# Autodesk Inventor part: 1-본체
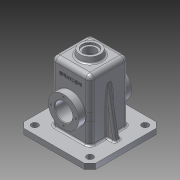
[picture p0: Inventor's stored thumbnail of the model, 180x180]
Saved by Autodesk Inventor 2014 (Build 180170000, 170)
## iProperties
Created: 2016-02
Part Number: 1-본체
Material: 알루미늄 6061
Document SubType Name: Modeling
Designer: 703-04
Density: 2.71 g/cm^3
Appearance: 알루미늄 - 평지
Mass: 932.849 g
Surface Area: 1043.49 cm^2
Volume: 344.225 cm^3
Author: 703-04
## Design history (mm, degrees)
sketch "스케치1"
  geometry: L1 (-65, 65)-(65, 65); L2 (65, 65)-(65, -65); L3 (65, -65)-(-65, -65); L4 (-65, -65)-(-65, 65); 1 further point
  constraints: 8 end point, 2 parallel, 1 horizontal, 1 perpendicular
  dimensions: "d0" = 130 distance of L2.end L3.end; "d1" = 65 distance from line of point (0, 0) L4; "d2" = 65 distance from line of point (0, 0) L1; "d3" = 130 distance between parallel lines of L3 L1
extrude "돌출1" new body sketch "스케치1" distance "d4" = 10; taper "d5" = 0 deg
chamfer "모따기1" distance "d6" = 10; stored, may be unused: second distance "d7" = 2, angle "d8" = 45 deg
sketch "스케치2"
  geometry: L1 (-35, 35)-(35, 35); L2 (35, 35)-(35, -35); L3 (35, -35)-(-35, -35); L4 (-35, -35)-(-35, 35); 1 further point
  constraints: 8 end point, 2 parallel, 1 horizontal, 1 perpendicular
  dimensions: "d9" = 35 distance from line of point (0, 0) L1; "d10" = 70 distance between parallel lines of L3 L1; "d11" = 35 distance from line of point (0, 0) L4; "d12" = 70 distance between parallel lines of L2 L4
extrude "돌출2" join sketch "스케치2" distance "d13" = 110; taper "d14" = 0 deg
node "작업 평면1"
sketch "스케치4"
  geometry: L1 (0, 0)-(0, 131.974); L2 (-55, 0)-(55, 0) reference; L3 (-58, 55)-(58, 55); C1 r 27.5 at (0, 55)
  constraints: 4 end point, 1 centre point, 1 midpoint, 1 parallel, 1 perpendicular, 1 point on line
  dimensions: "d18" = 55 diameter of C1; "d19" = 55 distance between parallel lines of L2 L3
extrude "돌출3" join sketch "스케치4" stored distance "d20" = 96; taper "d21" = 0 deg
hole "구멍1" diameter "d24" = 32; stored, may be unused: countersink angle "d28" = 90 deg, drill point angle "d30" = 118 deg; dims "d22" = 10, "d23" = 10, "d25" = 6, "d26" = 4, "d27" = 2, "d29" = 8
sketch "스케치6"
  geometry: L1 (-55, 0)-(55, 0) reference; L2 (-30, 115)-(30, 115); L3 (30, 115)-(30, 0); L4 (30, 0)-(-30, 0); L5 (-30, 0)-(-30, 115); L6 (-35, 10)-(-35, 120) reference; L7 (35, 120)-(-35, 120) reference; L8 (35, 10)-(35, 120) reference; 1 further point
  constraints: 8 end point, 2 parallel, 1 horizontal, 1 perpendicular, 1 point on line
  dimensions: "d33" = 30 distance from line of point (0, 0) L5; "d34" = 30 distance from line of point (0, 0) L3; "d35" = 115 distance of L2.end L3.end
extrude "돌출4" cut sketch "스케치6" stored distance "d36" = 60; taper "d37" = 0 deg
sketch "스케치7"
  geometry: C1 r 20 at (0, 0); 1 further point
  constraints: 1 centre point, 1 coincident
  dimensions: "d38" = 40 diameter of C1
extrude "돌출5" join sketch "스케치7" distance "d39" = 10; taper "d40" = -10 deg
hole "구멍2" diameter "d43" = 21; stored, may be unused: countersink angle "d47" = 90 deg, drill point angle "d49" = 0 deg; dims "d41" = 10, "d42" = 10, "d44" = 6, "d45" = 28, "d46" = 4, "d48" = 15
sketch "스케치8"
  geometry: L1 (35, 10)-(35, 120) reference; L2 (35, 95.069)-(50, 10); L3 (-55, 10)-(55, 10) reference; L4 (65, 0)-(65, 10) reference; 1 further point
  constraints: 2 end point, 2 point on line
  dimensions: "d50" = 10 deg angle of L4 L2; "d51" = 15 distance from line of L2.end L4
feature "리브1" sketch "스케치8" dims "d52" = 1, "d53" = 10, "d54" = 0, "d55" = 0, "d56" = 1, "d57" = 1
node "작업축1"
node "작업축2"
node "작업 평면2"
sketch "스케치9"
  geometry: L1 (-51.5, 48)-(-51.5, 30) reference; L2 (-7.5, 30)-(-122.5, 30) reference; L3 (-148.5, 0)-(33.5, 0) reference; L4 (-67.5, -91)-(-67.5, 91) reference; L5 (-112.5, 35)-(-2.5, 35) reference; L6 (-51.5, 30)-(-40, 30); L7 (-40, 30)-(-47, 23); L8 (-47, 23)-(-51.5, 23); L9 (-51.5, 23)-(-51.5, 30); L10 (-40, 30)-(-51.5, 30); 1 further point
  constraints: 10 end point, 1 collinear, 1 parallel, 1 perpendicular, 1 point on line
  dimensions: "d59" = 7 distance between parallel lines of L8 L10; "d60" = 27.5 distance from line of L4 L6.end; "d61" = 135 deg angle of L7 L2
revolve "회전1" sketch "스케치9" stored, may be unused: angle "d62" = 90 deg
sketch "스케치10" dims "d63" = 45
  geometry: L1 (0, -81)-(0, 101) reference; C1 r 27.5 at (0, 0) reference; 3 further points
  constraints: 1 coincident, 1 point on line, 1 vertical alignment, 2 other
hole "구멍3" sketch "스케치10" at (0, 22.5) diameter "d64" = 3.242; stored, may be unused: countersink angle "d68" = 90 deg, drill point angle "d70" = 118 deg; dims "d65" = 8, "d66" = 28, "d67" = 4, "d69" = 10
fillet "모깎기1" dims "d71" = 0.5
fillet "모깎기2" dims "d72" = 0.5
fillet "모깎기3" dims "d76" = 0.5
fillet "모깎기4" dims "d77" = 0.5
sketch "스케치11"
  geometry: L1 (-50, 50)-(50, 50); L2 (50, 50)-(50, -50); L3 (50, -50)-(-50, -50); L4 (-50, -50)-(-50, 50); 5 further points
  constraints: 8 end point, 4 coincident, 2 parallel, 1 horizontal, 1 perpendicular
  dimensions: "d78" = 100 distance between parallel lines of L3 L1; "d79" = 50 distance from line of L1 point (0, 0); "d80" = 100 distance between parallel lines of L4 L2; "d81" = 50 distance from line of point (0, 0) L4
hole "구멍4" sketch "스케치11" at (-50, 50), (-50, -50), (50, -50), (50, 50) diameter "d82" = 12; stored, may be unused: countersink angle "d86" = 90 deg, drill point angle "d88" = 118 deg; dims "d83" = 8, "d84" = 28, "d85" = 4, "d87" = 10
fillet "모깎기5" dims "d89" = 8
fillet "모깎기6" dims "d90" = 8
fillet "모깎기7" dims "d91" = 3
fillet "모깎기8" dims "d92" = 3
chamfer "모따기2" distance "d93" = 1; stored, may be unused: second distance "d94" = 2, angle "d95" = 45 deg
fillet "모깎기9" dims "d96" = 3
fillet "모깎기10" dims "d97" = 3
fillet "모깎기11" dims "d98" = 3
fillet "모깎기12" dims "d99" = 3
fillet "모깎기13" dims "d100" = 3
fillet "모깎기14" dims "d101" = 3
node "작업 평면3"
sketch "스케치12"
  geometry: L1 (-17.83, 54.906)-(17.83, 54.906); L2 (17.83, 54.906)-(17.83, 35.094); L3 (17.83, 35.094)-(-17.83, 35.094); L4 (-17.83, 35.094)-(-17.83, 54.906); L5 (0, -81)-(0, 101) reference; L6 (-17.83, 45)-(17.83, 45); L7 (0, 54.906)-(0, 35.094); L8 (-48, 45)-(54, 45); L9 (-18.237, 75)-(18.237, 75) reference; 1 further point
  constraints: 6 end point, 4 midpoint, 2 collinear, 1 perpendicular, 2 other
  dimensions: "d103" = 30 distance between parallel lines of L8 L9
feature "엠보싱1" sketch "스케치12" dims "d104" = 0.5, "d105" = 0
node "솔리드1"
mirror "대칭1"
mirror "대칭2"
pattern_circular "원형 패턴1" dims angle "d74" = 360 deg
mirror "대칭3"
mirror "대칭4"
other parameters: "d17" = 0, "d58" = 90 deg
